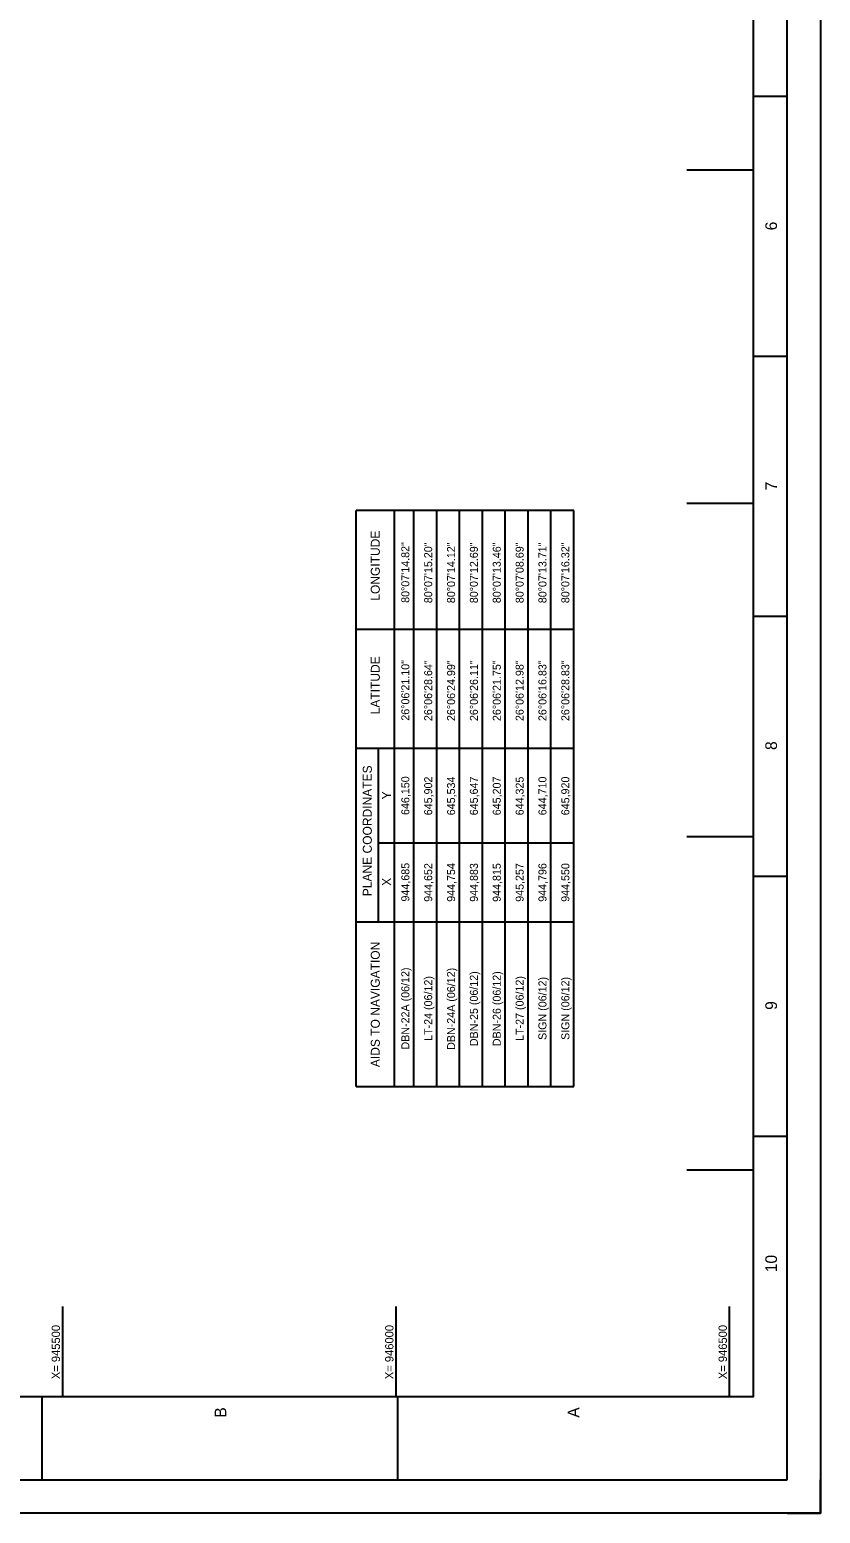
# Model space of a CAD drawing. Extents: x 943236 to 946636, y 643485 to 647885.
# Drawn here: x 945451 to 946636, y 643485 to 645710 of the extents above; entities that cross this region are included whole.
import ezdxf

# ---------------------------------------------------------------- set-up
doc = ezdxf.new("R2010")
doc.units = 0
for name, color, linetype in [('G-ANNO-NPLT', 7, 'Continuous'), ('G-ANNO-TTLB', 7, 'Continuous'), ('V-ANNO-SCHD', 7, 'Continuous'), ('V-ANNO-SYMB', 7, 'Continuous'), ('V-TOPO-COOR-STAT', 7, 'Continuous')]:
    doc.layers.add(name, color=color, linetype=linetype)

msp = doc.modelspace()

# ---------------------------------------------------------------- linework, layer by layer
at = {"layer": 'G-ANNO-NPLT'}
msp.add_lwpolyline([(943236.1, 643485.2), (943236.1, 647885.2), (946636.1, 647885.2), (946636.1, 643485.2)], close=True, dxfattribs=at)
msp.add_lwpolyline([(946586.1, 643485.2), (946636.1, 643485.2), (946636.1, 643535.2)], dxfattribs=at)
at = {"layer": 'G-ANNO-TTLB'}
for p, q in [((946586.1, 645610.2), (946536.1, 645610.2)), ((946586.1, 645220.2), (946536.1, 645220.2)), ((946586.1, 644830.2), (946536.1, 644830.2)), ((946586.1, 644440.2), (946536.1, 644440.2)), ((946586.1, 644050.2), (946536.1, 644050.2)), ((945469.5, 643535.2), (945469.5, 643660.2)), ((946002.8, 643535.2), (946002.8, 643660.2))]:
    msp.add_line(p, q, dxfattribs=at)
for points in [[(946586.1, 643535.2), (946586.1, 647835.2), (943286.1, 647835.2), (943286.1, 643535.2)], [(943336.1, 647785.2), (943336.1, 643660.2), (946536.1, 643660.2), (946536.1, 647785.2)]]:
    msp.add_lwpolyline(points, close=True, dxfattribs=at)
at = {"layer": 'V-ANNO-SCHD'}
for p, q in [((945939.9, 644125.5), (945939.9, 644989.5)), ((946266.4, 644989.5), (945939.9, 644989.5)), ((945997.7, 644125.5), (945997.7, 644989.5)), ((946026.5, 644125.5), (946026.5, 644989.5)), ((946060.8, 644125.5), (946060.8, 644989.1)), ((946095.1, 644125.5), (946095.1, 644989.1)), ((946129.3, 644125.5), (946129.3, 644989.1)), ((946163.6, 644125.5), (946163.6, 644989.1)), ((946197.9, 644125.5), (946197.9, 644989.1)), ((946232.2, 644125.5), (946232.2, 644989.1)), ((946266.4, 644125.5), (946266.4, 644989.5)), ((945939.9, 644811.2), (946266.4, 644811.2)), ((945939.9, 644632.9), (946266.4, 644632.9)), ((945973.6, 644372.2), (945973.6, 644632.9)), ((945973.6, 644491), (946266.4, 644491)), ((945939.9, 644372.2), (946266.4, 644372.2)), ((945939.9, 644125.5), (946266.4, 644125.5))]:
    msp.add_line(p, q, dxfattribs=at)
at = {"layer": 'V-TOPO-COOR-STAT'}
for p, q in [((946536.1, 645500), (946436.1, 645500)), ((946536.1, 645000), (946436.1, 645000)), ((946536.1, 644500), (946436.1, 644500)), ((946536.1, 644000), (946436.1, 644000)), ((945500, 643660.2), (945500, 643795.2)), ((946000, 643660.2), (946000, 643795.2)), ((946500, 643660.2), (946500, 643795.2))]:
    msp.add_line(p, q, dxfattribs=at)

# ---------------------------------------------------------------- texts
at = {"layer": 'G-ANNO-TTLB'}
for s, p in [('6', (946571.1, 645409.5)), ('7', (946571.1, 645019.5)), ('8', (946571.1, 644630.1)), ('9', (946571.1, 644240.3)), ('10', (946571.1, 643846.8)), ('B', (945745.4, 643628.7)), ('A', (946274.9, 643628.6))]:
    msp.add_text(s, height=17.5, rotation=90, dxfattribs=at).set_placement(p)
at = {"layer": 'V-ANNO-SCHD'}
for s, height, p in [('LONGITUDE', 13.47, (945975.5, 644854)), ('LATITUDE', 13.47, (945975.5, 644683.6)), ('PLANE COORDINATES', 13.471, (945963.5, 644410.8)), ('Y', 13.5, (945992.4, 644556)), ('X', 13.5, (945992.4, 644426.3)), ('AIDS TO NAVIGATION', 13.471, (945975.5, 644154.4))]:
    msp.add_text(s, height=height, rotation=90.0001, dxfattribs=at).set_placement(p)
at = {"layer": 'V-ANNO-SYMB'}
for s, p in [('80%%D07\'14.82"', (946019.8, 644850.8)), ('80%%D07\'15.20"', (946054.1, 644850.3)), ('80%%D07\'14.12"', (946088.4, 644850.3)), ('80%%D07\'12.69"', (946122.6, 644850.3)), ('80%%D07\'13.46"', (946156.9, 644850.3)), ('80%%D07\'08.69"', (946191.2, 644850.3)), ('80%%D07\'13.71"', (946225.4, 644850.3)), ('80%%D07\'16.32"', (946259.7, 644850.3)), ('26%%D06\'21.10"', (946019.8, 644674)), ('26%%D06\'28.64"', (946054.1, 644673.5)), ('26%%D06\'24.99"', (946088.4, 644673.5)), ('26%%D06\'26.11"', (946122.6, 644673.5)), ('26%%D06\'21.75"', (946156.9, 644673.5)), ('26%%D06\'12.98"', (946191.2, 644673.5)), ('26%%D06\'16.83"', (946225.4, 644673.5)), ('26%%D06\'28.83"', (946259.7, 644673.5)), ('646,150', (946019.8, 644532.6)), ('645,902', (946054.1, 644532.2)), ('645,534', (946088.4, 644532.2)), ('645,647', (946122.6, 644532.2)), ('645,207', (946156.9, 644532.2)), ('644,325', (946191.2, 644532.1)), ('644,710', (946225.4, 644532.2)), ('645,920', (946259.7, 644532.2)), ('944,685', (946019.8, 644402.8)), ('944,652', (946054.1, 644402.4)), ('944,754', (946088.4, 644402.4)), ('944,883', (946122.6, 644402.4)), ('944,815', (946156.9, 644402.3)), ('945,257', (946191.2, 644402.4)), ('944,796', (946225.4, 644402.4)), ('944,550', (946259.7, 644402.4)), ('DBN-22A (06/12)', (946019.8, 644180.8)), ('LT-24 (06/12)', (946054.1, 644193.8)), ('DBN-24A (06/12)', (946088.4, 644180.3)), ('DBN-25 (06/12)', (946122.6, 644185.9)), ('DBN-26 (06/12)', (946156.9, 644185.9)), ('LT-27 (06/12)', (946191.2, 644193.8)), ('SIGN (06/12)', (946225.4, 644195.2)), ('SIGN (06/12)', (946259.7, 644195.2))]:
    msp.add_text(s, height=12, rotation=90, dxfattribs=at).set_placement(p)
at = {"layer": 'V-TOPO-COOR-STAT'}
for s, p in [('X= 945500', (945496, 643686.4)), ('X= 946000', (945996, 643686.4)), ('X= 946500', (946496, 643686.4))]:
    msp.add_text(s, height=12.5, rotation=90, dxfattribs=at).set_placement(p)

doc.saveas('drawing.dxf')
